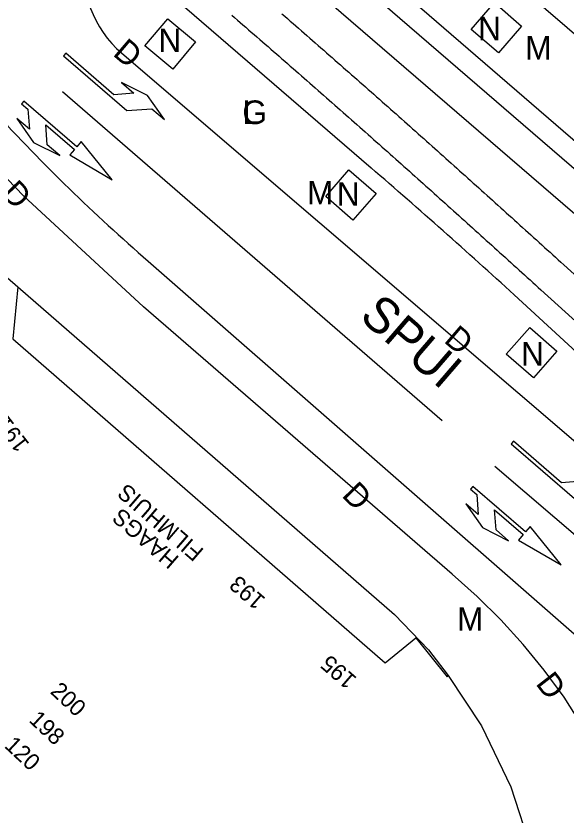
# Model space of a CAD drawing. Extents: x 81617 to 82144, y 454649 to 455150.
# Drawn here: x 81643.93 to 81667.23, y 454739.6 to 454773.41 of the extents above; entities that cross this region are included whole.
import ezdxf

# ---------------------------------------------------------------- set-up
doc = ezdxf.new("R2010")
doc.units = 0
doc.layers.add('B-WE-OG-TOPOGRAFIE-G', color=7, linetype='Continuous')
doc.layers.add('B-WE-VW-MARKERING-G', color=7, linetype='Continuous')

msp = doc.modelspace()

# ---------------------------------------------------------------- linework, layer by layer
at = {"layer": 'B-WE-OG-TOPOGRAFIE-G'}
for p, q in [((81644.004, 454761.954), (81659.963, 454748.087)), ((81665.037, 454761.611), (81680.379, 454747.473)), ((81659.963, 454748.087), (81661.403, 454746.591)), ((81661.403, 454746.591), (81662.234, 454745.51))]:
    msp.add_line(p, q, dxfattribs=at)
for points in [[(81675.253, 454761.521), (81640.069, 454791.86)], [(81680.676, 454755.662), (81639.378, 454791.23)], [(81679.74, 454754.574), (81638.311, 454790.255)], [(81635.238, 454787.447), (81658.972, 454766.985)], [(81681.559, 454760.501), (81679.141, 454762.728), (81658.73, 454780.256)], [(81664.464, 454747.862), (81663.46, 454748.853), (81662.405, 454749.789), (81649.33, 454761.105), (81644.243, 454765.8), (81642.536, 454767.561), (81634.314, 454776.58)], [(81665.344, 454772.99), (81664.366, 454771.852), (81663.215, 454772.841), (81664.192, 454773.979), (81665.344, 454772.99)], [(81653.072, 454773.446), (81653.19, 454773.344), (81653.308, 454773.242), (81653.426, 454773.14), (81653.544, 454773.038), (81653.662, 454772.936), (81653.78, 454772.833), (81653.898, 454772.731), (81654.016, 454772.629), (81654.134, 454772.526), (81654.252, 454772.424), (81654.37, 454772.322), (81654.488, 454772.219), (81654.605, 454772.117), (81654.723, 454772.015), (81654.841, 454771.912), (81654.959, 454771.81), (81655.076, 454771.707), (81655.194, 454771.605), (81655.312, 454771.502), (81655.429, 454771.4), (81655.429, 454771.4), (81655.547, 454771.297), (81655.665, 454771.194), (81655.783, 454771.091), (81655.901, 454770.988), (81656.019, 454770.885), (81656.137, 454770.781), (81656.255, 454770.678), (81656.373, 454770.575), (81656.49, 454770.472), (81656.608, 454770.369), (81656.726, 454770.265), (81656.844, 454770.162), (81656.961, 454770.059), (81657.079, 454769.955), (81657.197, 454769.852), (81657.314, 454769.749), (81657.432, 454769.645), (81657.549, 454769.542), (81657.667, 454769.438), (81657.784, 454769.335), (81657.902, 454769.231), (81658.019, 454769.128), (81658.137, 454769.024), (81658.254, 454768.92), (81658.371, 454768.817), (81658.489, 454768.713), (81658.606, 454768.609), (81658.723, 454768.505), (81658.841, 454768.401), (81658.958, 454768.298), (81659.075, 454768.194), (81659.192, 454768.09), (81659.309, 454767.986), (81659.426, 454767.882), (81659.544, 454767.778), (81659.661, 454767.674), (81659.778, 454767.57), (81659.895, 454767.466), (81660.012, 454767.362), (81660.129, 454767.258), (81660.245, 454767.153), (81660.362, 454767.049), (81660.479, 454766.945), (81660.596, 454766.841), (81660.596, 454766.841), (81660.713, 454766.737), (81660.829, 454766.633), (81660.945, 454766.529), (81661.062, 454766.425), (81661.178, 454766.321), (81661.294, 454766.216), (81661.411, 454766.112), (81661.527, 454766.008), (81661.643, 454765.904), (81661.759, 454765.8), (81661.875, 454765.696), (81661.992, 454765.591), (81662.108, 454765.487), (81662.224, 454765.383), (81662.34, 454765.278), (81662.456, 454765.174), (81662.572, 454765.07), (81662.688, 454764.965), (81662.804, 454764.861), (81662.921, 454764.756), (81663.037, 454764.652), (81663.153, 454764.547), (81663.269, 454764.443), (81663.385, 454764.338), (81663.501, 454764.234), (81663.617, 454764.129), (81663.733, 454764.025), (81663.849, 454763.92), (81663.965, 454763.815), (81664.08, 454763.711), (81664.196, 454763.606), (81664.312, 454763.502), (81664.428, 454763.397), (81664.544, 454763.292), (81664.66, 454763.188), (81664.776, 454763.083), (81664.892, 454762.978), (81665.008, 454762.873), (81665.124, 454762.769), (81665.24, 454762.664), (81665.356, 454762.559), (81665.472, 454762.455), (81665.587, 454762.35), (81665.703, 454762.245), (81665.819, 454762.14), (81665.935, 454762.035), (81666.051, 454761.931), (81666.167, 454761.826), (81666.167, 454761.826), (81691.328, 454739.082)], [(81655.193, 454773.508), (81655.311, 454773.405), (81655.429, 454773.303), (81655.547, 454773.2), (81655.665, 454773.097), (81655.783, 454772.995), (81655.901, 454772.892), (81656.019, 454772.789), (81656.137, 454772.687), (81656.255, 454772.584), (81656.373, 454772.481), (81656.373, 454772.481), (81656.491, 454772.378), (81656.609, 454772.275), (81656.727, 454772.171), (81656.846, 454772.068), (81656.964, 454771.965), (81657.082, 454771.861), (81657.2, 454771.758), (81657.318, 454771.655), (81657.436, 454771.551), (81657.554, 454771.448), (81657.672, 454771.344), (81657.79, 454771.241), (81657.908, 454771.137), (81658.026, 454771.033), (81658.144, 454770.93), (81658.262, 454770.826), (81658.38, 454770.722), (81658.498, 454770.619), (81658.615, 454770.515), (81658.733, 454770.411), (81658.851, 454770.307), (81658.969, 454770.204), (81659.086, 454770.1), (81659.204, 454769.996), (81659.322, 454769.892), (81659.439, 454769.788), (81659.557, 454769.684), (81659.674, 454769.58), (81659.792, 454769.476), (81659.91, 454769.372), (81660.027, 454769.268), (81660.144, 454769.163), (81660.262, 454769.059), (81660.379, 454768.955), (81660.497, 454768.851), (81660.614, 454768.746), (81660.731, 454768.642), (81660.849, 454768.538), (81660.966, 454768.433), (81661.083, 454768.329), (81661.2, 454768.225), (81661.317, 454768.12), (81661.435, 454768.016), (81661.552, 454767.911), (81661.552, 454767.911), (81661.668, 454767.807), (81661.785, 454767.703), (81661.902, 454767.598), (81662.018, 454767.494), (81662.135, 454767.39), (81662.251, 454767.286), (81662.368, 454767.181), (81662.484, 454767.077), (81662.601, 454766.972), (81662.717, 454766.868), (81662.834, 454766.764), (81662.95, 454766.659), (81663.067, 454766.555), (81663.183, 454766.45), (81663.299, 454766.346), (81663.416, 454766.241), (81663.532, 454766.137), (81663.648, 454766.032), (81663.764, 454765.928), (81663.881, 454765.823), (81663.997, 454765.718), (81664.113, 454765.614), (81664.229, 454765.509), (81664.345, 454765.404), (81664.461, 454765.3), (81664.578, 454765.195), (81664.694, 454765.09), (81664.81, 454764.986), (81664.926, 454764.881), (81665.042, 454764.776), (81665.158, 454764.672), (81665.274, 454764.567), (81665.39, 454764.462), (81665.506, 454764.357), (81665.622, 454764.253), (81665.738, 454764.148), (81665.854, 454764.043), (81665.97, 454763.938), (81666.086, 454763.833), (81666.202, 454763.729), (81666.318, 454763.624), (81666.434, 454763.519), (81666.55, 454763.414), (81666.666, 454763.31), (81666.782, 454763.205), (81666.897, 454763.1), (81667.013, 454762.995), (81667.129, 454762.89), (81667.129, 454762.89), (81692.29, 454740.147)], [(81651.53, 454772.316), (81650.568, 454771.165), (81649.394, 454772.147), (81650.356, 454773.298), (81651.53, 454772.316)], [(81648.409, 454771.836), (81673.57, 454750.3)], [(81617.371, 454754.911), (81625.886, 454752.89), (81625.842, 454755.692), (81626.197, 454758.472), (81626.813, 454760.795), (81627.343, 454762.377), (81628.233, 454763.789), (81629.433, 454764.949), (81630.873, 454765.792), (81632.218, 454766.193), (81634.01, 454770.641), (81644.004, 454761.954), (81643.799, 454759.75), (81659.561, 454746.045), (81660.871, 454747.097), (81662.19, 454745.455), (81662.234, 454745.51), (81663.642, 454743.374), (81664.894, 454740.79), (81665.775, 454738.056)], [(81659.185, 454765.907), (81658.203, 454764.773), (81657.047, 454765.775), (81658.03, 454766.908), (81659.185, 454765.907)], [(81666.834, 454759.229), (81665.844, 454758.102), (81664.698, 454759.11), (81665.688, 454760.236), (81666.834, 454759.229)], [(81670.568, 454738.214), (81669.091, 454741.249), (81668.201, 454742.903), (81667.143, 454744.591), (81666.308, 454745.728), (81665.415, 454746.82), (81664.464, 454747.862)]]:
    msp.add_lwpolyline(points, dxfattribs=at)
for centre, radius, start, end in [((81651.577, 454775.461), 4.814, 173.1117, 228.846), ((81464.19, 454541.058), 298.3, 47.67736, 49.23391)]:
    msp.add_arc(centre, radius, start, end, dxfattribs=at)
at = {"layer": 'B-WE-VW-MARKERING-G'}
for p, q in [((81646.036, 454771.842), (81645.938, 454771.729)), ((81645.938, 454771.729), (81648.626, 454769.411)), ((81648.081, 454770.079), (81646.036, 454771.842)), ((81649.501, 454770.043), (81648.397, 454770.599)), ((81648.397, 454770.599), (81648.927, 454770.142)), ((81648.927, 454770.142), (81648.081, 454770.079)), ((81650.214, 454769.032), (81649.501, 454770.043)), ((81644.266, 454769.808), (81644.168, 454769.694)), ((81644.168, 454769.694), (81644.434, 454769.466)), ((81646.501, 454767.882), (81644.266, 454769.808)), ((81644.434, 454769.466), (81644.496, 454768.619)), ((81648.626, 454769.411), (81649.684, 454769.489)), ((81649.684, 454769.489), (81650.214, 454769.032)), ((81644.496, 454768.619), (81643.966, 454769.077)), ((81643.966, 454769.077), (81644.679, 454768.066)), ((81645.254, 454767.966), (81645.191, 454768.813)), ((81645.191, 454768.813), (81646.403, 454767.768)), ((81644.679, 454768.066), (81645.784, 454767.509)), ((81645.784, 454767.509), (81645.254, 454767.966)), ((81646.697, 454768.109), (81646.501, 454767.882)), ((81648.004, 454766.486), (81646.697, 454768.109)), ((81646.403, 454767.768), (81646.207, 454767.541)), ((81646.207, 454767.541), (81648.004, 454766.486)), ((81649.533, 454763.036), (81669.519, 454745.553)), ((81664.997, 454755.427), (81664.899, 454755.313)), ((81667.042, 454753.664), (81664.997, 454755.427)), ((81664.899, 454755.313), (81667.588, 454752.995)), ((81671.474, 454748.14), (81664.21, 454754.35)), ((81667.888, 454753.726), (81667.042, 454753.664)), ((81663.278, 454753.505), (81663.18, 454753.392)), ((81663.18, 454753.392), (81663.446, 454753.163)), ((81665.513, 454751.579), (81663.278, 454753.505)), ((81663.446, 454753.163), (81663.508, 454752.317)), ((81663.508, 454752.317), (81662.978, 454752.774)), ((81662.978, 454752.774), (81663.691, 454751.763)), ((81664.266, 454751.664), (81664.203, 454752.51)), ((81664.203, 454752.51), (81665.415, 454751.466)), ((81663.691, 454751.763), (81664.796, 454751.207)), ((81665.709, 454751.806), (81665.513, 454751.579)), ((81667.016, 454750.184), (81665.709, 454751.806)), ((81664.796, 454751.207), (81664.266, 454751.664)), ((81665.415, 454751.466), (81665.219, 454751.238)), ((81665.219, 454751.238), (81667.016, 454750.184))]:
    msp.add_line(p, q, dxfattribs=at)
msp.add_lwpolyline([(81661.98, 454756.288), (81645.894, 454770.207)], dxfattribs=at)
msp.add_arc((81701.944, 454823.477), 80, 222.55062, 229.06996, dxfattribs=at)

# ---------------------------------------------------------------- texts
at = {"layer": 'B-WE-OG-TOPOGRAFIE-G'}
for s, p in [('N', (81663.508, 454772.386)), ('N', (81649.963, 454771.884)), ('M', (81665.499, 454771.567)), ('G', (81653.52, 454768.84)), ('L', (81653.52, 454768.84)), ('M', (81656.258, 454765.438)), ('N', (81657.523, 454765.381)), ('N', (81665.324, 454758.617)), ('M', (81662.612, 454747.396))]:
    msp.add_text(s, height=1, dxfattribs=at).set_placement(p)
for s, height, rotation, p in [('D', 1, 319.4397, (81647.989, 454771.775)), ('D', 1, 314.115, (81643.277, 454765.864)), ('SPUI', 1.5, 319.2077, (81658.427, 454760.619)), ('D', 1, 319.4397, (81662.013, 454759.638)), ('191', 0.7, 127.6954, (81644.529, 454755.301)), ('D', 1, 314.115, (81657.692, 454753.102)), ('FILMHUIS', 0.7, 139.2287, (81651.931, 454750.815)), ('HAAGS', 0.7, 139.2287, (81650.882, 454750.49)), ('193', 0.7, 138.9808, (81654.54, 454748.756)), ('195', 0.7, 138.9808, (81658.403, 454745.396)), ('D', 1, 307.7353, (81665.91, 454745.158)), ('200', 0.7, 316.9258, (81645.344, 454744.784)), ('198', 0.7, 316.9258, (81644.439, 454743.576)), ('120', 0.7, 316.9258, (81643.403, 454742.491))]:
    msp.add_text(s, height=height, rotation=rotation, dxfattribs=at).set_placement(p)

doc.saveas('drawing.dxf')
